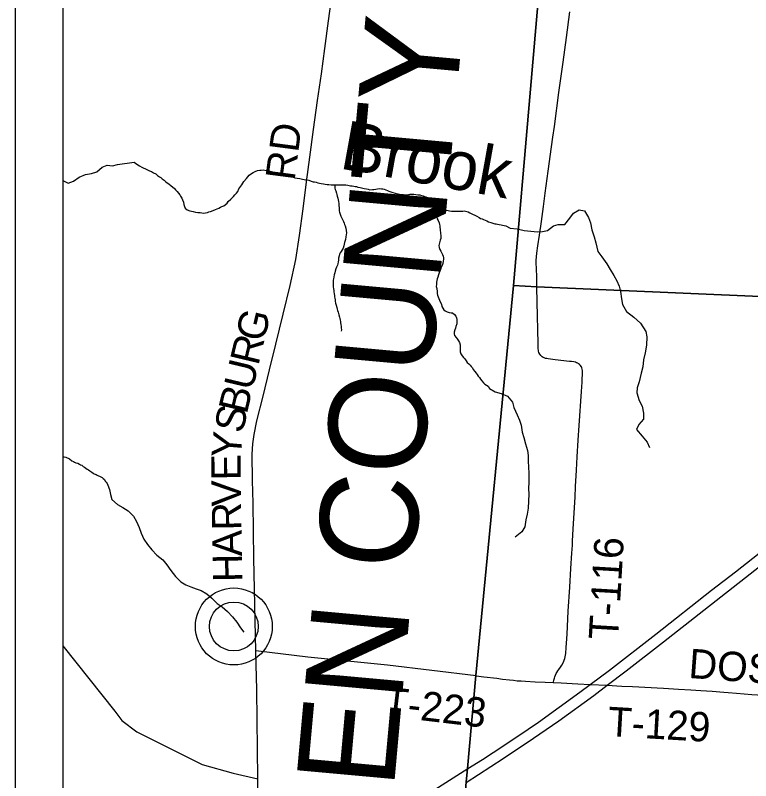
# Model space of a CAD drawing. Extents: x 0 to 34, y 0 to 22.
# Drawn here: x 2.17 to 3.593, y 14.472 to 15.952 of the extents above; entities that cross this region are included whole.
import ezdxf

# ---------------------------------------------------------------- set-up
doc = ezdxf.new("R2010")
doc.units = 0
for name, color, linetype in [('Default', 7, 'Continuous'), ('GM_X_County_Road', 7, 'Continuous'), ('GM_X_County_Road_Text', 7, 'Continuous'), ('GM_X_County_Text', 7, 'Continuous'), ('GM_X_Interstate_Route', 7, 'Continuous'), ('GM_X_Minor_River', 7, 'Continuous'), ('GM_X_Minor_River_Text', 7, 'Continuous'), ('GM_X_Township_Road', 7, 'Continuous'), ('GM_X_Township_Road_Text', 7, 'Continuous'), ('GM_X_Unincorporated', 7, 'Continuous'), ('GM_X_Unincorporated_Location', 7, 'Continuous'), ('SH_Cut_Line', 7, 'Continuous'), ('SH_Data', 7, 'Continuous')]:
    doc.layers.add(name, color=color, linetype=linetype)

msp = doc.modelspace()

# ---------------------------------------------------------------- linework, layer by layer
at = {"layer": 'Default'}
for points in [[(2.2621, 19.2337), (2.2621, 13.6252), (2.9696, 13.6252), (3.0429, 14.4692), (3.0457, 14.4958), (3.0617, 14.6751), (3.1343, 15.4291), (3.1974, 16.1596), (3.2667, 16.919), (3.2768, 17.1355), (3.47, 19.2407)], [(3.47, 19.2407), (3.2768, 17.1355), (3.2667, 16.919), (3.1974, 16.1596), (3.1343, 15.4291), (3.1796, 15.4266), (4.2078, 15.3826), (4.2393, 15.3805), (4.819, 15.349), (5.5157, 15.319), (7.9465, 15.1727), (8.1234, 15.1688), (8.137, 15.3372), (8.146, 15.4642), (8.2031, 16.209), (8.2895, 16.85), (8.3286, 17.3076), (8.3307, 17.3314), (8.3334, 17.361), (8.3935, 18.0719)]]:
    msp.add_lwpolyline(points, dxfattribs=at)
msp.add_lwpolyline([(2.9696, 13.6252), (8.4279, 13.6252), (8.4024, 15.1386), (8.4023, 15.1576), (8.3761, 15.1587), (8.1234, 15.1688), (7.9465, 15.1727), (5.5157, 15.319), (4.819, 15.349), (4.2393, 15.3805), (4.2078, 15.3826), (3.1796, 15.4266), (3.1343, 15.4291), (3.0617, 14.6751), (3.0457, 14.4958), (3.0429, 14.4692)], close=True, dxfattribs=at)
at = {"layer": 'GM_X_County_Road'}
msp.add_lwpolyline([(2.6413, 14.3985), (2.6397, 14.4752), (2.6391, 14.5337), (2.6387, 14.589), (2.638, 14.6484), (2.6364, 14.696), (2.6356, 14.7231), (2.6343, 14.7807), (2.6331, 14.8428), (2.6321, 14.9013), (2.6313, 14.9544), (2.6305, 15.0083), (2.6297, 15.0523), (2.6289, 15.103), (2.6298, 15.1234), (2.6325, 15.1413), (2.638, 15.1678), (2.6499, 15.2151), (2.6625, 15.266), (2.6746, 15.3157), (2.6889, 15.3737), (2.7021, 15.4292), (2.7132, 15.4797), (2.7206, 15.5262), (2.7276, 15.5779), (2.7342, 15.6299), (2.7402, 15.6774), (2.7475, 15.7311), (2.7555, 15.7872), (2.7627, 15.8387), (2.7695, 15.8879), (2.7767, 15.9414), (2.7837, 15.9931)], dxfattribs=at)
at = {"layer": 'GM_X_Interstate_Route'}
for points in [[(3.0431, 14.4687), (3.1143, 14.5147), (3.1733, 14.5539), (3.2223, 14.5879), (3.2897, 14.6367), (3.3158, 14.6564), (3.3526, 14.6843), (3.4248, 14.7403), (3.503, 14.8017), (3.7624, 15.0055), (3.8499, 15.0742), (3.9079, 15.1201), (4.0947, 15.2666), (4.2253, 15.3689), (4.2395, 15.3799), (4.3589, 15.4744), (4.4405, 15.5374), (4.4967, 15.5795), (4.5605, 15.6251), (4.6204, 15.6663), (4.6952, 15.7154), (4.7561, 15.754)], [(3.0459, 14.4952), (3.0745, 14.5128), (3.0953, 14.5264), (3.143, 14.5578), (3.1831, 14.5852), (3.2631, 14.6431), (3.2831, 14.658), (3.3199, 14.6854), (3.4098, 14.7551), (3.5176, 14.8402), (3.5637, 14.8759), (3.698, 14.9817), (3.7624, 15.0324), (3.9135, 15.1509), (4.0748, 15.2775), (4.1843, 15.3634), (4.208, 15.3821), (4.2706, 15.4316), (4.3525, 15.4963), (4.4288, 15.5551), (4.5036, 15.6106), (4.5522, 15.6452), (4.6483, 15.7105), (4.7069, 15.7479)], [(2.2621, 14.1085), (2.2942, 14.1207), (2.3651, 14.1479), (2.4211, 14.1705), (2.4563, 14.1852), (2.5187, 14.2126), (2.5817, 14.2413), (2.644, 14.2706), (2.7039, 14.3004), (2.7655, 14.3325), (2.8252, 14.3644), (2.8715, 14.3903), (2.9436, 14.4324), (2.989, 14.4597), (3.0459, 14.4952)]]:
    msp.add_lwpolyline(points, dxfattribs=at)
at = {"layer": 'GM_X_Minor_River'}
for points in [[(2.2621, 15.6325), (2.273, 15.6274), (2.2833, 15.631), (2.2941, 15.6388), (2.3063, 15.644), (2.3177, 15.6461), (2.3284, 15.6493), (2.3384, 15.6582), (2.3483, 15.6619), (2.3586, 15.661), (2.3683, 15.663)], [(2.3683, 15.663), (2.4003, 15.6676), (2.4029, 15.6661), (2.4056, 15.6638), (2.4109, 15.661), (2.4154, 15.6583), (2.418, 15.6568), (2.4225, 15.6548), (2.4274, 15.6525), (2.4301, 15.6513), (2.4339, 15.6497), (2.4376, 15.6474), (2.4421, 15.645), (2.4459, 15.6423), (2.4493, 15.6396), (2.4519, 15.6381), (2.4545, 15.6357), (2.4583, 15.6327), (2.4613, 15.6303), (2.4643, 15.628), (2.4673, 15.6257), (2.4718, 15.6222), (2.4748, 15.6199), (2.4782, 15.6172), (2.4804, 15.6145), (2.4834, 15.611), (2.4864, 15.608), (2.489, 15.6049), (2.4901, 15.6022), (2.4924, 15.598), (2.4938, 15.5953), (2.4957, 15.5908), (2.4967, 15.5862), (2.4978, 15.582), (2.4989, 15.5786), (2.503, 15.5755), (2.5083, 15.5739), (2.5114, 15.5731), (2.5148, 15.5723), (2.5193, 15.5714), (2.5235, 15.5706), (2.528, 15.5702), (2.5311, 15.5698), (2.5337, 15.5693), (2.5383, 15.5697), (2.5421, 15.5707), (2.5451, 15.5715), (2.5482, 15.5725), (2.5535, 15.5744), (2.5581, 15.5762), (2.5612, 15.5773), (2.5642, 15.5788), (2.5673, 15.5806), (2.5703, 15.5821), (2.5738, 15.5836), (2.5765, 15.5851), (2.5803, 15.5888), (2.5826, 15.5918), (2.5873, 15.5963), (2.5927, 15.6015), (2.595, 15.6045), (2.5984, 15.6079), (2.6008, 15.6113), (2.6031, 15.6162), (2.6047, 15.6188), (2.6085, 15.6237), (2.6128, 15.6305), (2.6178, 15.6365), (2.6228, 15.6425), (2.6275, 15.6462), (2.6305, 15.6477), (2.6347, 15.6499), (2.6389, 15.6514), (2.6435, 15.6525), (2.6462, 15.6524), (2.6503, 15.6527), (2.6556, 15.6519), (2.6598, 15.6511), (2.6636, 15.6503), (2.6662, 15.6499), (2.6689, 15.6491), (2.6719, 15.6486), (2.6749, 15.6478), (2.6795, 15.6466), (2.6821, 15.6458), (2.6859, 15.6446), (2.6889, 15.6438), (2.692, 15.643), (2.6954, 15.6422), (2.6988, 15.641), (2.7033, 15.6398), (2.7079, 15.6386), (2.7113, 15.6378)], [(2.7113, 15.6378), (2.7158, 15.637), (2.7207, 15.6362), (2.726, 15.635), (2.7291, 15.6342), (2.7328, 15.6334), (2.7385, 15.6329), (2.7427, 15.6313), (2.7468, 15.6301), (2.7495, 15.6297), (2.7525, 15.6289), (2.7559, 15.6281), (2.7593, 15.6273), (2.7624, 15.6265), (2.7665, 15.6257), (2.7703, 15.6252), (2.7741, 15.6248), (2.7768, 15.6244), (2.7817, 15.6243), (2.7859, 15.6239), (2.7885, 15.6238), (2.7927, 15.6242), (2.7957, 15.6241), (2.7984, 15.6241), (2.8033, 15.624), (2.8071, 15.624), (2.8098, 15.6239), (2.814, 15.6231), (2.8166, 15.6227), (2.8193, 15.6223), (2.8223, 15.6219), (2.8253, 15.6214), (2.828, 15.621), (2.8306, 15.6206), (2.8333, 15.6198), (2.8378, 15.619), (2.8405, 15.6182), (2.8431, 15.6178), (2.8458, 15.617), (2.8503, 15.6161), (2.8533, 15.6153), (2.8567, 15.6145), (2.8613, 15.6149), (2.864, 15.6152), (2.8681, 15.6159), (2.8742, 15.6169), (2.8788, 15.6165), (2.8814, 15.6161), (2.8841, 15.6157), (2.8905, 15.6133), (2.8935, 15.6117), (2.8969, 15.6106), (2.9011, 15.6094), (2.9053, 15.6082), (2.9079, 15.6074), (2.9113, 15.6066), (2.914, 15.6061), (2.9181, 15.6053), (2.9215, 15.6053), (2.9261, 15.6048), (2.931, 15.6055), (2.9337, 15.6059), (2.9379, 15.6058), (2.9417, 15.6058), (2.9455, 15.6053), (2.9493, 15.6049), (2.953, 15.6045), (2.9565, 15.6036), (2.9595, 15.6028), (2.9621, 15.6017), (2.9648, 15.6005), (2.967, 15.5978), (2.9734, 15.5943), (2.976, 15.592), (2.9783, 15.5893), (2.9813, 15.5858), (2.9827, 15.5828), (2.9861, 15.5805), (2.9895, 15.5785), (2.9937, 15.5769), (2.9975, 15.5765), (3.0012, 15.5757), (3.0046, 15.5749), (3.0081, 15.5744), (3.0107, 15.574), (3.0145, 15.5732), (3.0179, 15.5732), (3.0206, 15.5731), (3.0255, 15.5734), (3.0304, 15.5734), (3.0331, 15.5733), (3.0361, 15.5733), (3.0388, 15.5736), (3.0418, 15.5732), (3.0464, 15.5716), (3.0501, 15.5697), (3.0528, 15.5685), (3.0554, 15.5673), (3.0596, 15.5654), (3.0633, 15.5634), (3.0679, 15.5607)], [(2.7885, 15.6238), (2.7884, 15.6178), (2.7895, 15.6151), (2.7906, 15.6124), (2.7917, 15.6082), (2.7924, 15.6052), (2.7935, 15.6021), (2.7946, 15.5979), (2.795, 15.5953), (2.7957, 15.5915), (2.7964, 15.588), (2.7963, 15.5843), (2.797, 15.5793), (2.797, 15.5767), (2.7973, 15.5736), (2.7976, 15.5709), (2.7991, 15.5671), (2.8002, 15.5637), (2.8017, 15.5606), (2.8043, 15.5557), (2.8054, 15.553), (2.8068, 15.5499), (2.8076, 15.5473), (2.8087, 15.5446), (2.8097, 15.5404), (2.8108, 15.5355), (2.8111, 15.5309), (2.8107, 15.5275), (2.8103, 15.5233), (2.8094, 15.5184), (2.8074, 15.5123), (2.807, 15.5093), (2.8062, 15.5059), (2.8046, 15.5018), (2.8031, 15.498), (2.8007, 15.495), (2.7992, 15.4923), (2.798, 15.4897), (2.7972, 15.4867), (2.796, 15.4825), (2.7956, 15.4783), (2.7951, 15.4749), (2.7947, 15.4715), (2.7939, 15.4689), (2.792, 15.4651), (2.7904, 15.4617), (2.7892, 15.4568), (2.7888, 15.4538), (2.7876, 15.45), (2.7868, 15.4458), (2.7859, 15.4424), (2.7855, 15.4394), (2.7855, 15.4367), (2.7854, 15.4337), (2.7858, 15.4303), (2.7857, 15.4268), (2.7864, 15.4227), (2.7868, 15.4196), (2.7871, 15.417), (2.7874, 15.4132), (2.7881, 15.4101), (2.7881, 15.4075), (2.7884, 15.4048), (2.7892, 15.4017), (2.7891, 15.3991), (2.7902, 15.3953), (2.7913, 15.3911), (2.7924, 15.3869), (2.7935, 15.3838), (2.7942, 15.3808), (2.7953, 15.3781), (2.796, 15.3755), (2.7967, 15.3724), (2.7978, 15.3682), (2.7981, 15.3656), (2.7989, 15.3625), (2.7996, 15.3598), (2.7995, 15.3572), (2.8006, 15.3541), (2.801, 15.3503), (2.8009, 15.3477), (2.8013, 15.3439), (2.8012, 15.3408)], [(2.9827, 15.5828), (2.9838, 15.5778), (2.9838, 15.5744), (2.9841, 15.571), (2.9848, 15.5683), (2.9855, 15.5649), (2.9862, 15.5618), (2.9869, 15.558), (2.9884, 15.555), (2.9903, 15.5508), (2.9913, 15.5473), (2.9917, 15.5447), (2.992, 15.5413), (2.9924, 15.5386), (2.9927, 15.5359), (2.9934, 15.5321), (2.9934, 15.5295), (2.9937, 15.5264), (2.9937, 15.523), (2.9936, 15.5204), (2.9928, 15.5173), (2.992, 15.5143), (2.9908, 15.509), (2.99, 15.5064), (2.9903, 15.5029), (2.9922, 15.4987), (2.9937, 15.4957), (2.9951, 15.493), (2.997, 15.4892), (2.9981, 15.4861), (2.9988, 15.4831), (2.9987, 15.4804), (2.9983, 15.4766), (2.9975, 15.4721), (2.9967, 15.4679), (2.9939, 15.4627), (2.9931, 15.4596), (2.992, 15.457), (2.9908, 15.4536), (2.9896, 15.4502), (2.988, 15.4453), (2.9868, 15.4423), (2.986, 15.4388), (2.9856, 15.4358), (2.9855, 15.4316), (2.9851, 15.4275), (2.9858, 15.4237), (2.9865, 15.4176), (2.9868, 15.4138), (2.9875, 15.4107), (2.9886, 15.4073), (2.9901, 15.4042), (2.9912, 15.4008), (2.9923, 15.3978), (2.9949, 15.3932), (2.9959, 15.389), (2.9978, 15.3855), (2.9996, 15.3825), (3.0023, 15.3802), (3.006, 15.3782), (3.0102, 15.3774), (3.014, 15.3766), (3.0166, 15.3762), (3.02, 15.3734), (3.023, 15.37), (3.0241, 15.3666), (3.0248, 15.3639), (3.0251, 15.3593), (3.0251, 15.3555), (3.0231, 15.3502), (3.0223, 15.3468), (3.0207, 15.3434), (3.0195, 15.3389), (3.0195, 15.3359), (3.0202, 15.3324), (3.0232, 15.329), (3.0254, 15.3263), (3.028, 15.3225), (3.0299, 15.319), (3.031, 15.3148), (3.0313, 15.3114), (3.0312, 15.3072), (3.0312, 15.3042), (3.0311, 15.3008), (3.0326, 15.297), (3.0348, 15.2935), (3.0374, 15.2904), (3.0401, 15.2874), (3.0427, 15.2839), (3.0449, 15.2805), (3.0479, 15.2778), (3.0505, 15.2754), (3.0528, 15.2728), (3.0554, 15.2701), (3.0561, 15.267), (3.0595, 15.2632), (3.0621, 15.2601), (3.0639, 15.2574), (3.0662, 15.254), (3.0684, 15.2513), (3.0706, 15.2482)], [(3.1277, 15.5405), (3.1418, 15.5388), (3.1553, 15.5358), (3.1678, 15.5341), (3.181, 15.5334), (3.1905, 15.534), (3.2, 15.5357), (3.2116, 15.5446), (3.2211, 15.5474), (3.234, 15.5472), (3.2433, 15.5595), (3.2507, 15.5692), (3.2615, 15.5755), (3.272, 15.5737), (3.2793, 15.5607), (3.2833, 15.5504), (3.286, 15.5367), (3.2903, 15.5233), (3.2939, 15.5118), (3.2977, 15.4951), (3.3051, 15.4847), (3.315, 15.4712), (3.3216, 15.4605), (3.3286, 15.4486), (3.3344, 15.4382), (3.3387, 15.4279), (3.3412, 15.4176), (3.3432, 15.4039), (3.3456, 15.3928), (3.3533, 15.3794), (3.3675, 15.3681), (3.3805, 15.3565), (3.3904, 15.3404), (3.3924, 15.3301), (3.3921, 15.3142), (3.3895, 15.299), (3.3858, 15.2854), (3.3844, 15.2722), (3.3815, 15.2597), (3.3774, 15.2431), (3.3737, 15.2314), (3.3732, 15.2216), (3.3774, 15.2071), (3.3832, 15.196), (3.386, 15.1823), (3.3861, 15.1709), (3.3768, 15.1604), (3.3725, 15.1507), (3.3836, 15.1379), (3.3932, 15.1267), (3.3979, 15.116)], [(3.0679, 15.5607), (3.0709, 15.5591), (3.0735, 15.5583), (3.0765, 15.5572), (3.0796, 15.5556), (3.0826, 15.5544), (3.086, 15.5525), (3.0909, 15.5509), (3.0947, 15.5497), (3.0981, 15.5489), (3.1011, 15.5485), (3.1038, 15.548), (3.1064, 15.5473), (3.1106, 15.5464), (3.1132, 15.546), (3.1166, 15.5456), (3.1193, 15.5448), (3.1277, 15.5405)], [(3.0706, 15.2482), (3.0729, 15.2451), (3.0762, 15.2409), (3.0792, 15.2386), (3.0822, 15.2367), (3.0853, 15.2347), (3.0883, 15.2302), (3.0989, 15.2239)], [(3.0989, 15.2239), (3.1106, 15.2207), (3.123, 15.2151), (3.1322, 15.2036), (3.135, 15.1933), (3.1416, 15.1795), (3.1459, 15.1692), (3.1495, 15.1592), (3.1515, 15.1459), (3.1543, 15.1352), (3.1578, 15.123), (3.1617, 15.1101), (3.1631, 15.1005), (3.1625, 15.0888), (3.1634, 15.0789), (3.1643, 15.066), (3.1639, 15.0493), (3.1633, 15.0368), (3.1638, 15.0262), (3.1635, 15.0121), (3.1625, 14.9989), (3.1608, 14.9875), (3.1586, 14.9766), (3.1565, 14.963), (3.1506, 14.9528), (3.1379, 14.9428)], [(2.2621, 15.0979), (2.2629, 15.098), (2.2652, 15.098), (2.2682, 15.0975), (2.2705, 15.0964), (2.2728, 15.0952), (2.275, 15.0944), (2.2799, 15.0905), (2.2829, 15.0893), (2.2852, 15.0881), (2.2878, 15.0865), (2.2912, 15.0857), (2.2946, 15.0837), (2.2969, 15.0829), (2.2992, 15.0818), (2.3018, 15.0794), (2.3044, 15.0782), (2.307, 15.0759), (2.3097, 15.0743), (2.3123, 15.0728), (2.3149, 15.0708), (2.3183, 15.0685), (2.3209, 15.0665), (2.3232, 15.0653), (2.3266, 15.0641), (2.3288, 15.0626), (2.3311, 15.0614), (2.3334, 15.0606), (2.336, 15.0594), (2.3383, 15.0582), (2.3405, 15.0563), (2.3428, 15.0543), (2.3446, 15.0513), (2.3461, 15.0489), (2.3479, 15.0463), (2.3498, 15.0436)], [(2.3498, 15.0436), (2.3528, 15.035), (2.3549, 15.0255), (2.3574, 15.0159), (2.3685, 15.0059), (2.3787, 15.0003), (2.3891, 14.994), (2.3991, 14.9836), (2.405, 14.9732), (2.4104, 14.9614), (2.414, 14.9507), (2.4191, 14.9392), (2.4261, 14.9288), (2.4349, 14.918), (2.4446, 14.9079), (2.4558, 14.899), (2.4635, 14.8893), (2.4716, 14.8782), (2.4801, 14.867), (2.4909, 14.8565), (2.5006, 14.8506), (2.5104, 14.8467), (2.5201, 14.843), (2.5303, 14.8398), (2.5408, 14.8335), (2.5508, 14.825), (2.5612, 14.8145), (2.5709, 14.8079), (2.581, 14.7993), (2.5906, 14.7885), (2.5988, 14.7785), (2.6065, 14.7677), (2.6126, 14.7589)]]:
    msp.add_lwpolyline(points, dxfattribs=at)
at = {"layer": 'GM_X_Township_Road'}
for points in [[(3.1798, 15.426), (3.1793, 15.4444), (3.1789, 15.4636), (3.1786, 15.4712), (3.1786, 15.478), (3.1791, 15.4851), (3.1798, 15.4918), (3.1816, 15.5058), (3.1846, 15.527), (3.1883, 15.5533), (3.1922, 15.5819), (3.1957, 15.6081), (3.2015, 15.6502), (3.208, 15.6972), (3.2106, 15.7159), (3.2135, 15.7368), (3.2224, 15.8024), (3.2249, 15.8206), (3.2304, 15.8611), (3.2371, 15.9088), (3.2434, 15.9584)], [(3.2114, 14.6618), (3.2116, 14.6627), (3.2125, 14.6664), (3.2135, 14.6699), (3.2143, 14.6725), (3.2157, 14.6761), (3.2171, 14.6791), (3.2184, 14.6813), (3.2205, 14.6845), (3.2224, 14.6871), (3.2255, 14.6914), (3.2279, 14.6953), (3.2306, 14.7001), (3.2318, 14.7028), (3.2327, 14.7052), (3.2337, 14.7083), (3.2343, 14.7111), (3.235, 14.7147), (3.2354, 14.718), (3.2365, 14.7297), (3.237, 14.738), (3.238, 14.7552), (3.2405, 14.7994), (3.2432, 14.846), (3.2454, 14.8823), (3.2474, 14.9117), (3.2484, 14.9271), (3.2489, 14.9354), (3.2501, 14.9583), (3.2518, 14.9896), (3.2535, 15.0201), (3.2546, 15.0406), (3.2563, 15.0721), (3.2577, 15.0979), (3.2597, 15.1305), (3.2615, 15.1586), (3.2658, 15.2241), (3.2672, 15.2423), (3.2676, 15.2481), (3.268, 15.2577), (3.2681, 15.2609), (3.2679, 15.2649), (3.2675, 15.2677), (3.2667, 15.2702), (3.2658, 15.2722), (3.2637, 15.2751), (3.2623, 15.2765), (3.2605, 15.278), (3.2587, 15.2791), (3.2564, 15.2801), (3.2541, 15.2809), (3.2509, 15.2817), (3.2469, 15.2823), (3.2428, 15.2827), (3.2148, 15.2858), (3.2063, 15.2869), (3.2016, 15.2875), (3.199, 15.288), (3.1966, 15.2885), (3.194, 15.2894), (3.1919, 15.2903), (3.1899, 15.2917), (3.1871, 15.2943), (3.1852, 15.2968), (3.1837, 15.2997), (3.1828, 15.3027), (3.1825, 15.3043), (3.1822, 15.3069), (3.182, 15.3102), (3.1821, 15.317), (3.1804, 15.3972), (3.1798, 15.426)], [(2.2621, 14.7329), (2.3632, 14.6062), (2.3766, 14.5886), (2.4058, 14.5665), (2.5317, 14.5031), (2.5921, 14.4863), (2.6397, 14.4752)], [(3.0619, 14.6746), (2.8909, 14.6955), (2.7365, 14.7107), (2.6356, 14.7231)], [(3.0619, 14.6746), (3.0769, 14.6729), (3.1023, 14.6699), (3.1133, 14.6685), (3.127, 14.6669), (3.1344, 14.666), (3.1416, 14.6653), (3.149, 14.6647), (3.1579, 14.6641), (3.1765, 14.6632), (3.1959, 14.6623), (3.2114, 14.6618)], [(3.2114, 14.6618), (3.2267, 14.661), (3.2592, 14.6592), (3.2831, 14.658), (3.3158, 14.6564), (3.3439, 14.655), (3.3645, 14.6539), (3.4244, 14.6507), (3.4535, 14.6491), (3.4777, 14.6478), (3.4971, 14.6466), (3.5191, 14.6449), (3.5413, 14.6431), (3.5496, 14.6424), (3.5658, 14.6411), (3.581, 14.6399), (3.5954, 14.6388), (3.6174, 14.6372), (3.6425, 14.6354), (3.671, 14.6332), (3.7819, 14.6247), (3.8426, 14.6201), (3.9002, 14.6157), (3.9112, 14.6148)]]:
    msp.add_lwpolyline(points, dxfattribs=at)
at = {"layer": 'GM_X_Unincorporated'}
for radius in [0.0744, 0.0472]:
    msp.add_circle((2.5933, 14.7701), radius, dxfattribs=at)
at = {"layer": 'GM_X_Unincorporated_Location'}
msp.add_line((2.5933, 14.7701), (2.5933, 14.7701), dxfattribs=at)
at = {"layer": 'SH_Cut_Line'}
for points in [[(3.5682, 20.4252), (2.2621, 20.4252), (2.2621, 13.6252), (2.9696, 13.6252), (3.0429, 14.4692), (3.0457, 14.4958), (3.0617, 14.6751), (3.1343, 15.4291), (3.1974, 16.1596), (3.2667, 16.919), (3.2768, 17.1355), (3.47, 19.2407), (3.4748, 19.2963), (3.4903, 19.4759), (3.4966, 19.5464), (3.5066, 19.6647), (3.5092, 19.6961), (3.5125, 19.7343), (3.5169, 19.7823), (3.5231, 19.8516), (3.5424, 20.1754)], [(2.9696, 13.6252), (9.0621, 13.6252), (9.0621, 20.4252), (3.5682, 20.4252), (3.5424, 20.1754), (3.5231, 19.8516), (3.5169, 19.7823), (3.5125, 19.7343), (3.5092, 19.6961), (3.5066, 19.6647), (3.4966, 19.5464), (3.4903, 19.4759), (3.4748, 19.2963), (3.47, 19.2407), (3.2768, 17.1355), (3.2667, 16.919), (3.1974, 16.1596), (3.1343, 15.4291), (3.0617, 14.6751), (3.0457, 14.4958), (3.0429, 14.4692)]]:
    msp.add_lwpolyline(points, close=True, dxfattribs=at)
at = {"layer": 'SH_Data'}
msp.add_line((2.1704, 20.5628), (2.1704, 13.5628), dxfattribs=at)

# ---------------------------------------------------------------- texts
at = {"layer": 'GM_X_County_Road_Text'}
for s, height, rotation, p in [('RD', 0.05682, 82.569, (2.7107, 15.6309)), ('G', 0.0568, 76.6135, (2.6514, 15.3184)), ('R', 0.0568, 76.6084, (2.6406, 15.273)), ('U', 0.0568, 76.6114, (2.629, 15.2243)), ('B', 0.0568, 76.6207, (2.6182, 15.1789)), ('S', 0.0568, 78.2437, (2.6105, 15.1418)), ('Y', 0.0568, 84.8969, (2.6063, 15.0937)), ('E', 0.0568, 90.3386, (2.6066, 15.0527)), ('V', 0.0568, 90.8852, (2.6074, 15.0028)), ('R', 0.0568, 90.8855, (2.6081, 14.9561)), ('A', 0.0568, 90.8843, (2.6089, 14.9061)), ('H', 0.0568, 90.8852, (2.6097, 14.8562))]:
    msp.add_text(s, height=height, rotation=rotation, dxfattribs=at).set_placement(p)
at = {"layer": 'GM_X_County_Text'}
msp.add_text('WARREN COUNTY', height=0.189394, rotation=84.812, dxfattribs=at).set_placement((2.8327, 13.6837))
at = {"layer": 'GM_X_Minor_River_Text'}
msp.add_text('Brook', height=0.09469, rotation=349.756, dxfattribs=at).set_placement((2.7957, 15.6561))
at = {"layer": 'GM_X_Township_Road_Text'}
for s, rotation, p in [('T-116', 86.6346, (3.3365, 14.7433)), ('DOSTER', 355.8161, (3.472, 14.6707)), ('T-223', 353.2579, (2.8813, 14.5976)), ('T-129', 356.6664, (3.3156, 14.5583))]:
    msp.add_text(s, height=0.05682, rotation=rotation, dxfattribs=at).set_placement(p)

doc.saveas('drawing.dxf')
